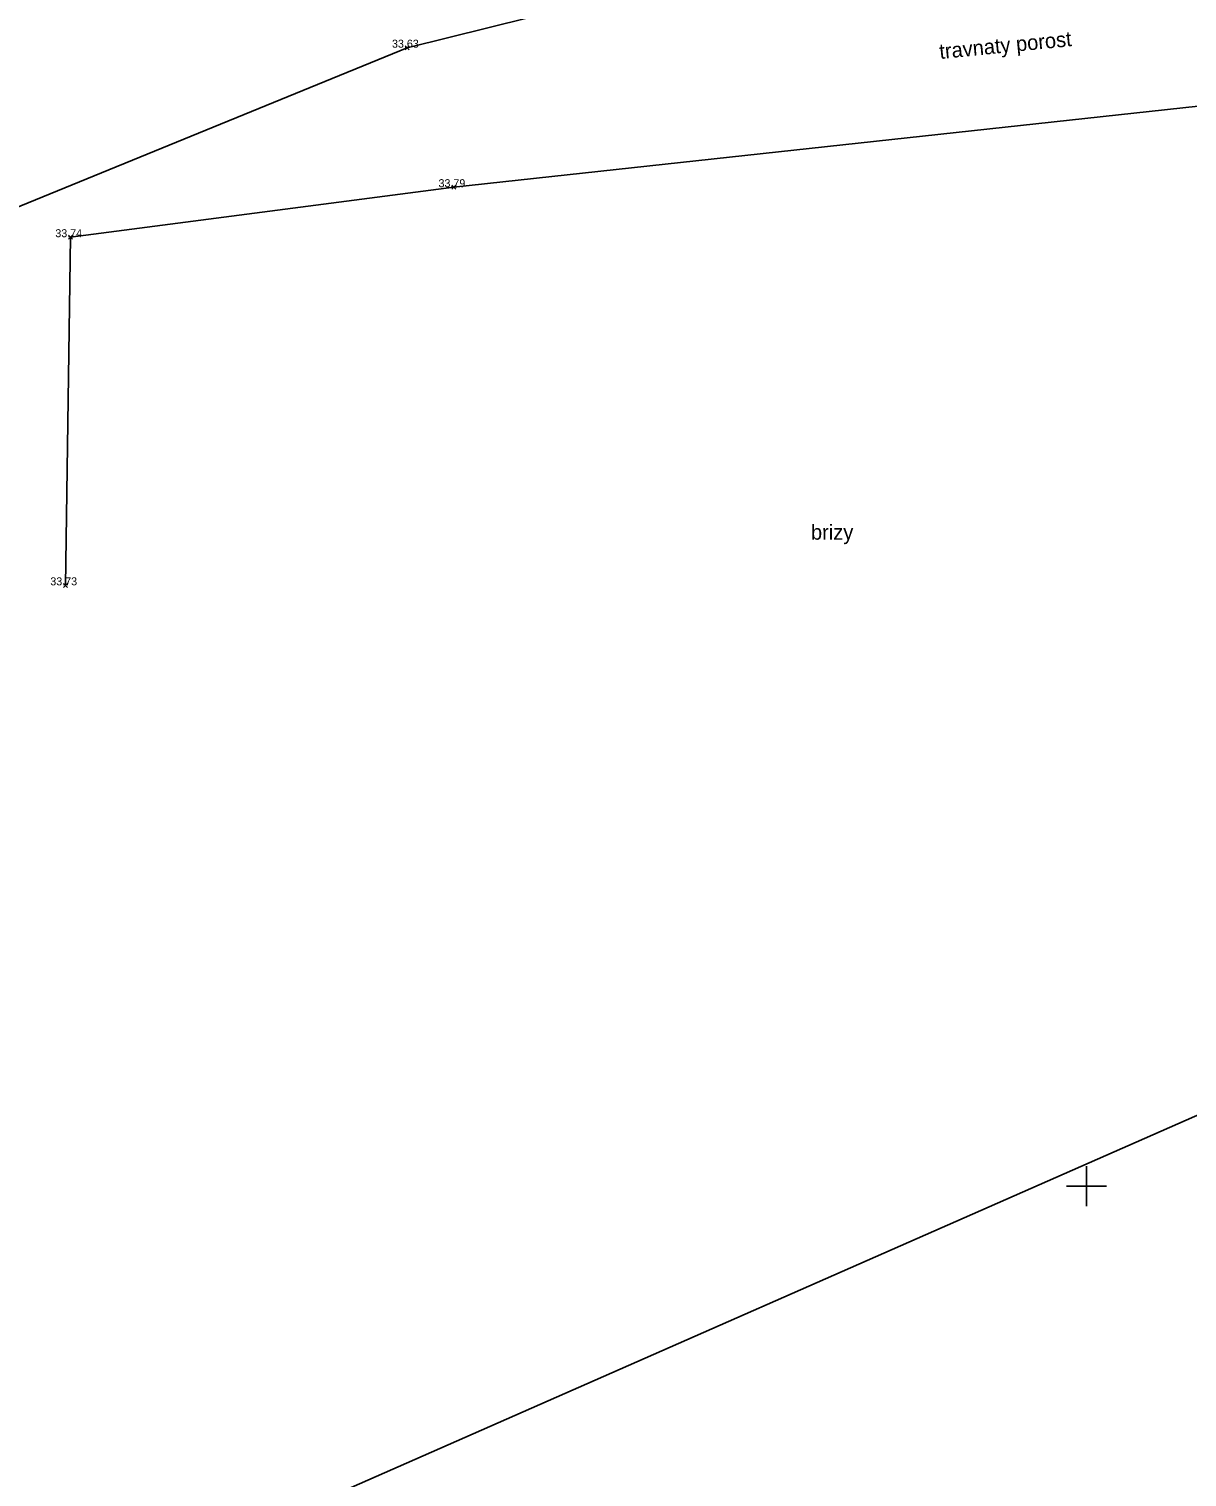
# Model space of a CAD drawing. Extents: x -772865 to -772533, y -1034366 to -1034132.
# Drawn here: x -772771.14 to -772747.99, y -1034305.82 to -1034276.87 of the extents above; entities that cross this region are included whole.
import ezdxf

# ---------------------------------------------------------------- set-up
doc = ezdxf.new("R2010")
doc.units = 0
for name, color, linetype in [('body', 7, 'Continuous'), ('KM_hranice', 7, 'Continuous'), ('mistni_popis', 7, 'Continuous'), ('oddeleni_ploch', 7, 'Continuous'), ('souradnicova_sit', 7, 'Continuous'), ('stromy_kere', 7, 'Continuous'), ('vyskove_koty', 7, 'Continuous')]:
    doc.layers.add(name, color=color, linetype=linetype)

msp = doc.modelspace()

# ---------------------------------------------------------------- linework, layer by layer
at = {"layer": 'body'}
for p, q in [((-772763.54, -1034277.28), (-772763.62, -1034277.2)), ((-772763.62, -1034277.28), (-772763.54, -1034277.2)), ((-772762.61, -1034280.07), (-772762.69, -1034279.99)), ((-772762.69, -1034280.07), (-772762.61, -1034279.99)), ((-772770.27, -1034281.07), (-772770.35, -1034280.99)), ((-772770.35, -1034281.07), (-772770.27, -1034280.99)), ((-772770.37, -1034288.03), (-772770.45, -1034287.95)), ((-772770.45, -1034288.03), (-772770.37, -1034287.95))]:
    msp.add_line(p, q, dxfattribs=at)
at = {"layer": 'KM_hranice'}
msp.add_line((-772736.19, -1034293.48), (-772790.73, -1034317.48), dxfattribs=at)
at = {"layer": 'oddeleni_ploch'}
msp.add_lwpolyline([(-772689.63, -1034259.88), (-772704.53, -1034266.45), (-772719.18, -1034273.09), (-772731.59, -1034278.63), (-772738.33, -1034281.57), (-772742.46, -1034279.19), (-772747.03, -1034275.55), (-772755.44, -1034275.22), (-772763.58, -1034277.24), (-772782.03, -1034284.79), (-772793.82, -1034291.56), (-772799.88, -1034296.39), (-772802.42, -1034299.52), (-772804.8, -1034304.37)], dxfattribs=at)
at = {"layer": 'souradnicova_sit'}
for p, q in [((-772750, -1034299.6), (-772750, -1034300.4)), ((-772750.4, -1034300), (-772749.6, -1034300))]:
    msp.add_line(p, q, dxfattribs=at)
at = {"layer": 'stromy_kere'}
msp.add_lwpolyline([(-772740.68, -1034295.27), (-772742.52, -1034289.67), (-772746.79, -1034278.3), (-772762.65, -1034280.03), (-772770.31, -1034281.03), (-772770.41, -1034287.99)], dxfattribs=at)

# ---------------------------------------------------------------- texts
at = {"layer": 'mistni_popis'}
msp.add_text('travnaty porost', height=0.3, rotation=5.615, dxfattribs=at).set_placement((-772752.929, -1034277.467))
msp.add_text('brizy', height=0.3, dxfattribs=at).set_placement((-772755.51, -1034287.077))
at = {"layer": 'vyskove_koty'}
for s, p in [('33.63', (-772763.885, -1034277.24)), ('33.79', (-772762.955, -1034280.03)), ('33.74', (-772770.615, -1034281.03)), ('33.73', (-772770.715, -1034287.99))]:
    msp.add_text(s, height=0.16, dxfattribs=at).set_placement(p)

doc.saveas('drawing.dxf')
